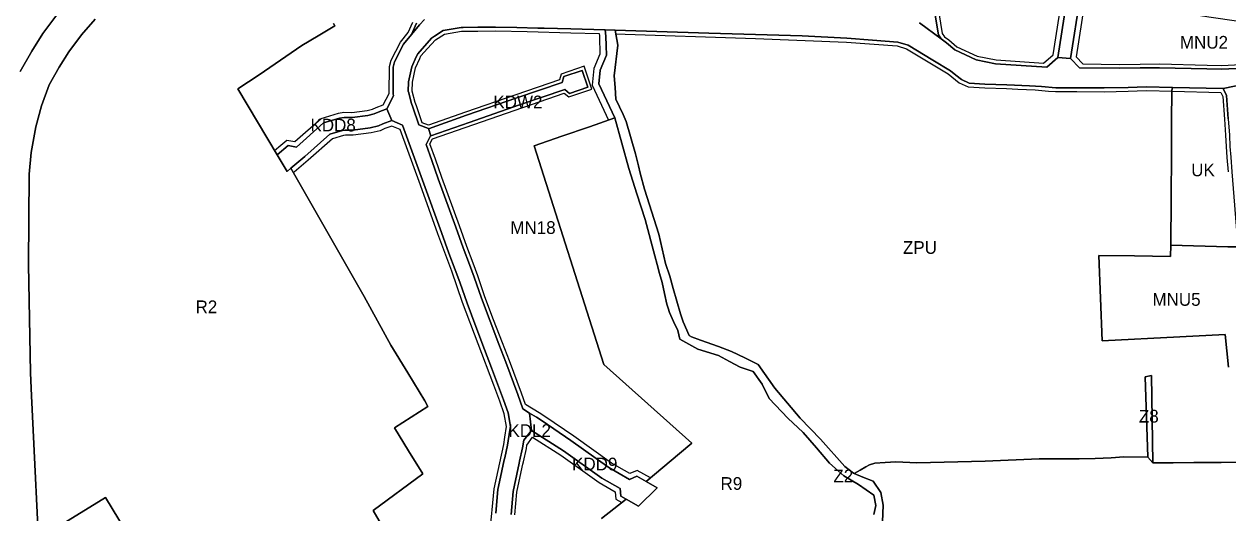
# Model space of a CAD drawing. Extents: x 7440055 to 7442242, y 5549003 to 5552256.
# Drawn here: x 7440555 to 7441503, y 5551138 to 5551522 of the extents above; entities that cross this region are included whole.
import ezdxf

# ---------------------------------------------------------------- set-up
doc = ezdxf.new("R2010")
doc.units = 0
for name, color, linetype in [('linie_rozgraniczajace', 7, 'Continuous'), ('linie_zabudowy_nieprzekraczalne', 7, 'Continuous'), ('oznaczenia_przeznaczen', 7, 'Continuous')]:
    doc.layers.add(name, color=color, linetype=linetype)

msp = doc.modelspace()

# ---------------------------------------------------------------- linework, layer by layer
at = {"layer": 'linie_rozgraniczajace'}
for points in [[(7441383.47, 5551585.26), (7441369.53, 5551496.02), (7441360.77, 5551488.28), (7441320.39, 5551491.07), (7441305.16, 5551494.15), (7441288.26, 5551501.88), (7441281.75, 5551507.55), (7441277.65, 5551510.58), (7441275.62, 5551513.88), (7441272.71, 5551530.74)], [(7441387.09, 5551543.58), (7441379.54, 5551495.17), (7441369.53, 5551496.02), (7441383.47, 5551585.26)], [(7440552.37, 5551484.85), (7440561.36, 5551501), (7440570.03, 5551514.74), (7440581.24, 5551529.61)], [(7440581.24, 5551529.61), (7440570.03, 5551514.74), (7440561.36, 5551501), (7440552.37, 5551484.85)], [(7440568.31, 5551084.03), (7440561.3, 5551229.74), (7440560.36, 5551247.97), (7440558.94, 5551333.21), (7440559.35, 5551404.19), (7440560.99, 5551421.23), (7440564.66, 5551441.32), (7440569.17, 5551457.85), (7440575.19, 5551474.44), (7440582.87, 5551488.25), (7440590.62, 5551500.52), (7440600.61, 5551513.79), (7440611.46, 5551526.06)], [(7440611.46, 5551526.06), (7440600.61, 5551513.79), (7440590.62, 5551500.52), (7440582.87, 5551488.25), (7440575.19, 5551474.44), (7440569.17, 5551457.85), (7440564.66, 5551441.32), (7440560.99, 5551421.23), (7440559.35, 5551404.19), (7440558.94, 5551333.21), (7440560.36, 5551247.97), (7440561.3, 5551229.74), (7440568.31, 5551084.03)], [(7440864.39, 5551522.89), (7440860.47, 5551514.03), (7440854.24, 5551506.48), (7440847.21, 5551492.58), (7440846.02, 5551488.33), (7440845.97, 5551467.36), (7440846.43, 5551465.88), (7440841.08, 5551455.6), (7440834.12, 5551453.05), (7440831.05, 5551451.58), (7440826.21, 5551450.42), (7440813.73, 5551448.76), (7440807.56, 5551448.87), (7440803.84, 5551448.27), (7440791.26, 5551444.5), (7440769.8, 5551425.47), (7440763.47, 5551426.67), (7440754.77, 5551419.34), (7440723.72, 5551471.36), (7440740.42, 5551482.41), (7440757.21, 5551493.91), (7440773.99, 5551505.41), (7440787, 5551513.13), (7440800.01, 5551520.84), (7440799.06, 5551522.6)], [(7440799.06, 5551522.6), (7440800.01, 5551520.84), (7440787, 5551513.13), (7440773.99, 5551505.41), (7440757.21, 5551493.91), (7440740.42, 5551482.41), (7440723.72, 5551471.36), (7440754.77, 5551419.34), (7440762.55, 5551406.31), (7440765.57, 5551408.85), (7440823.07, 5551307.95), (7440844.16, 5551269.66), (7440857.57, 5551247.82), (7440870.97, 5551225.98), (7440873.3, 5551221.47), (7440847.14, 5551204.57), (7440858.21, 5551186.49), (7440869.28, 5551168.42), (7440830.37, 5551139.67), (7440855.55, 5551096.35)], [(7440841.08, 5551455.6), (7440846.43, 5551465.88), (7440845.97, 5551467.36), (7440846.02, 5551488.33), (7440847.21, 5551492.58), (7440854.24, 5551506.48), (7440860.47, 5551514.03), (7440866.69, 5551521.58), (7440870.74, 5551525.79)], [(7440870.74, 5551525.79), (7440866.69, 5551521.58), (7440860.47, 5551514.03), (7440864.39, 5551522.89)], [(7441272.71, 5551530.74), (7441275.62, 5551513.88), (7441277.65, 5551510.58), (7441260.52, 5551523.24)], [(7441260.52, 5551523.24), (7441277.65, 5551510.58), (7441281.75, 5551507.55), (7441288.26, 5551501.88), (7441305.16, 5551494.15), (7441320.39, 5551491.07), (7441360.77, 5551488.28), (7441369.53, 5551496.02), (7441379.54, 5551495.17), (7441386.59, 5551487.9), (7441418.09, 5551487.55), (7441434.39, 5551487.74), (7441449.54, 5551487.92), (7441486.94, 5551487.06), (7441498.3, 5551486.67), (7441521.18, 5551487.82)], [(7441517.61, 5551475.36), (7441499.81, 5551471.5), (7441459.78, 5551472.46), (7441439.04, 5551472.95), (7441424.9, 5551472.43), (7441405.88, 5551471.99), (7441384.4, 5551472.11), (7441367.82, 5551472.16), (7441356.74, 5551473.02), (7441347.16, 5551473.76), (7441329.29, 5551474.56), (7441312.08, 5551475.02), (7441299.57, 5551475.72), (7441293.53, 5551478.67), (7441289.25, 5551482.12), (7441284.97, 5551485.58), (7441271.13, 5551493.91), (7441251.57, 5551505.53), (7441243.52, 5551508.12), (7441223.43, 5551509.64), (7441203.34, 5551511.15), (7441168.18, 5551512.88), (7441094.59, 5551515.18), (7441020.99, 5551517.47), (7441013.03, 5551517.77), (7440986.04, 5551518.48), (7440965.05, 5551518.98), (7440960.05, 5551519.09), (7440943.33, 5551519.46), (7440926.61, 5551519.83), (7440924.46, 5551519.89), (7440912.81, 5551519.77), (7440901.16, 5551519.65), (7440899.59, 5551519.64), (7440885.32, 5551517.28), (7440878.58, 5551512.84), (7440876.21, 5551511.27), (7440865.37, 5551498.82), (7440864.24, 5551496.37), (7440860.7, 5551488.71), (7440858.17, 5551476.9), (7440857.97, 5551469.18), (7440858.01, 5551469.07), (7440860.59, 5551459.78), (7440861.58, 5551457), (7440866.34, 5551443.07), (7440873.77, 5551440.02), (7440875.66, 5551434.26), (7440875.56, 5551434.23), (7440871.91, 5551427.55), (7440876.57, 5551414.95), (7440881.57, 5551400.63), (7440895.45, 5551362.45), (7440901.14, 5551346.29), (7440906.15, 5551333.12), (7440909.91, 5551323.26), (7440915.5, 5551306.79), (7440922.35, 5551288.57), (7440929.27, 5551270.45), (7440934.74, 5551256.2), (7440944.28, 5551230.79), (7440948.14, 5551219.49), (7440953.47, 5551216.3), (7440954.87, 5551202.51), (7440948.85, 5551195.01), (7440947.98, 5551188.98), (7440945.66, 5551178.47), (7440945.29, 5551176.84), (7440941.5, 5551159.61), (7440940.44, 5551154.55), (7440938.97, 5551136.46)], [(7441007.93, 5551475.12), (7441008.96, 5551486), (7441013.92, 5551497.72), (7441013.69, 5551505.16), (7441013.47, 5551512.61), (7441013.03, 5551517.77), (7441020.99, 5551517.47), (7441023.1, 5551505.78), (7441020.17, 5551481.56), (7441020.78, 5551472.39), (7441021.38, 5551463.21), (7441027.28, 5551451.22), (7441029.63, 5551445.5), (7441036.86, 5551420.19), (7441037.36, 5551418.15), (7441039.16, 5551410.84), (7441040.61, 5551404.89), (7441043.94, 5551392.31), (7441055.37, 5551357.09), (7441057.98, 5551345.56), (7441060.58, 5551334.02), (7441063.93, 5551324.03), (7441066.6, 5551314.17), (7441069.4, 5551304.23), (7441072.2, 5551294.3), (7441074.44, 5551288.02), (7441079.26, 5551277.23), (7441081.01, 5551276.13), (7441087.97, 5551273.64), (7441102.13, 5551268.56), (7441112.43, 5551264.68), (7441122.91, 5551259.64), (7441133.39, 5551254.59), (7441146.57, 5551235.75), (7441166.46, 5551212.18), (7441182.48, 5551195.8), (7441201.7, 5551174.39), (7441208.65, 5551169.02), (7441209.02, 5551168.74), (7441216.03, 5551165.84), (7441224.08, 5551162.79), (7441230.21, 5551153.9), (7441231.98, 5551143.95), (7441230.98, 5551117.63)], [(7441517.12, 5551177.56), (7441498.21, 5551177.47), (7441476.61, 5551177.35), (7441460.42, 5551177.25), (7441444.22, 5551177.16), (7441443.36, 5551245.71), (7441438.27, 5551244.8), (7441440.28, 5551181.48), (7441421.43, 5551181.89), (7441411.52, 5551181.14), (7441398.95, 5551180.66), (7441386.39, 5551180.17), (7441354.75, 5551180.31), (7441312.23, 5551178.44), (7441258.43, 5551177.15), (7441241.98, 5551178), (7441233.61, 5551177.4), (7441225.24, 5551176.81), (7441221.12, 5551175.51), (7441218.3, 5551173.93), (7441213.95, 5551171.5), (7441209.02, 5551168.74), (7441208.65, 5551169.02), (7441201.7, 5551174.39), (7441182.48, 5551195.8), (7441166.46, 5551212.18), (7441146.57, 5551235.75), (7441133.39, 5551254.59), (7441122.91, 5551259.64), (7441112.43, 5551264.68), (7441102.13, 5551268.56), (7441087.97, 5551273.64), (7441081.01, 5551276.13), (7441079.26, 5551277.23), (7441074.44, 5551288.02), (7441072.2, 5551294.3), (7441069.4, 5551304.23), (7441066.6, 5551314.17), (7441063.93, 5551324.03), (7441060.58, 5551334.02), (7441057.98, 5551345.56), (7441055.37, 5551357.09), (7441043.94, 5551392.31), (7441040.61, 5551404.89), (7441039.16, 5551410.84), (7441037.36, 5551418.15), (7441036.86, 5551420.19), (7441029.63, 5551445.5), (7441027.28, 5551451.22), (7441021.38, 5551463.21), (7441020.78, 5551472.39), (7441020.17, 5551481.56), (7441023.1, 5551505.78), (7441020.99, 5551517.47), (7441094.59, 5551515.18), (7441168.18, 5551512.88), (7441203.34, 5551511.15), (7441223.43, 5551509.64), (7441243.52, 5551508.12), (7441251.57, 5551505.53), (7441271.13, 5551493.91), (7441284.97, 5551485.58), (7441289.25, 5551482.12), (7441293.53, 5551478.67), (7441299.57, 5551475.72), (7441312.08, 5551475.02), (7441329.29, 5551474.56), (7441347.16, 5551473.76), (7441356.74, 5551473.02), (7441367.82, 5551472.16), (7441384.4, 5551472.11), (7441405.88, 5551471.99), (7441424.9, 5551472.43), (7441439.04, 5551472.95), (7441459.78, 5551472.46), (7441459.15, 5551470.04), (7441459.01, 5551445.55), (7441458.88, 5551421.05), (7441458.67, 5551384.69), (7441458.47, 5551348.32), (7441458.22, 5551339.48), (7441429.96, 5551339.88), (7441401.69, 5551340.27), (7441403.05, 5551306.63), (7441404.42, 5551272.98), (7441465.68, 5551276.14), (7441501.34, 5551277.98), (7441503.83, 5551252.33)], [(7441503.74, 5551447.63), (7441502.36, 5551466.11), (7441499.81, 5551471.5), (7441517.61, 5551475.36)], [(7441224.56, 5551136.62), (7441226.1, 5551143.57), (7441224.66, 5551151.71), (7441212.54, 5551160.19), (7441200.89, 5551166.81), (7441189.76, 5551176.86), (7441179.41, 5551188.94), (7441169.05, 5551201.03), (7441156.74, 5551212.26), (7441142.04, 5551227.85), (7441136.54, 5551238.91), (7441129.48, 5551249.06), (7441119.21, 5551252.35), (7441110.79, 5551256.96), (7441102.37, 5551261.58), (7441085.93, 5551266.65), (7441078.92, 5551270.57), (7441071.91, 5551274.48), (7441070.14, 5551281.3), (7441066.92, 5551288.37), (7441063.71, 5551295.45), (7441062.67, 5551298.73), (7441061.63, 5551302.02), (7441059.71, 5551310.46), (7441057.78, 5551318.9), (7441055.89, 5551326.18), (7441054.02, 5551333.12), (7441052.16, 5551340.05), (7441044.51, 5551368.57), (7441038.05, 5551388.68), (7441031.59, 5551408.78), (7441026.03, 5551428.58), (7441020.48, 5551448.38), (7441007.93, 5551475.12)], [(7440870.3, 5551396.52), (7440853.38, 5551442.77), (7440845, 5551446.38), (7440841.08, 5551455.6)], [(7440957.02, 5551426.53), (7440978.88, 5551434.05), (7441000.62, 5551441.54), (7441020.48, 5551448.38), (7441026.03, 5551428.58), (7441031.59, 5551408.78), (7441038.05, 5551388.68), (7441044.51, 5551368.57), (7441052.16, 5551340.05), (7441054.02, 5551333.12), (7441055.89, 5551326.18), (7441057.78, 5551318.9), (7441059.71, 5551310.46), (7441061.63, 5551302.02), (7441062.67, 5551298.73), (7441063.71, 5551295.45), (7441066.92, 5551288.37), (7441070.14, 5551281.3), (7441071.91, 5551274.48), (7441078.92, 5551270.57), (7441085.93, 5551266.65), (7441102.37, 5551261.58), (7441110.79, 5551256.96), (7441119.21, 5551252.35), (7441129.48, 5551249.06), (7441136.54, 5551238.91), (7441142.04, 5551227.85), (7441156.74, 5551212.26), (7441169.05, 5551201.03), (7441179.41, 5551188.94), (7441189.76, 5551176.86), (7441200.89, 5551166.81), (7441212.54, 5551160.19), (7441224.66, 5551151.71), (7441226.1, 5551143.57), (7441224.56, 5551136.62)], [(7440855.55, 5551096.35), (7440830.37, 5551139.67), (7440869.28, 5551168.42), (7440858.21, 5551186.49), (7440847.14, 5551204.57), (7440873.3, 5551221.47), (7440870.97, 5551225.98), (7440857.57, 5551247.82), (7440844.16, 5551269.66), (7440823.07, 5551307.95), (7440765.57, 5551408.85), (7440776.57, 5551418.11), (7440796.24, 5551435.55), (7440806.09, 5551438.5), (7440808.27, 5551438.86), (7440814.3, 5551438.75), (7440828.04, 5551440.58), (7440834.41, 5551442.1), (7440838.01, 5551443.83), (7440845, 5551446.38), (7440853.38, 5551442.77), (7440870.3, 5551396.52), (7440884.15, 5551358.41), (7440889.87, 5551342.16), (7440894.94, 5551328.85), (7440898.62, 5551319.19), (7440904.2, 5551302.74), (7440911.13, 5551284.32), (7440918.06, 5551266.16), (7440923.52, 5551251.94), (7440932.98, 5551226.74), (7440936.48, 5551216.5), (7440938.34, 5551205.77), (7440937.85, 5551202.89), (7440936.17, 5551191.13), (7440933.95, 5551181.1), (7440933.58, 5551179.46), (7440929.76, 5551162.12), (7440928.54, 5551156.26), (7440927.02, 5551137.61)], [(7441081.3, 5551192.61), (7441012.02, 5551254.53), (7440957.02, 5551426.53)], [(7440927.02, 5551137.61), (7440928.54, 5551156.26), (7440929.76, 5551162.12), (7440933.58, 5551179.46), (7440933.95, 5551181.1), (7440936.17, 5551191.13), (7440937.85, 5551202.89), (7440938.34, 5551205.77), (7440936.48, 5551216.5), (7440932.98, 5551226.74), (7440923.52, 5551251.94), (7440918.06, 5551266.16), (7440911.13, 5551284.32), (7440904.2, 5551302.74), (7440898.62, 5551319.19), (7440894.94, 5551328.85), (7440889.87, 5551342.16), (7440884.15, 5551358.41), (7440870.3, 5551396.52)], [(7441503.83, 5551252.33), (7441501.34, 5551277.98), (7441465.68, 5551276.14), (7441404.42, 5551272.98), (7441403.05, 5551306.63), (7441401.69, 5551340.27), (7441429.96, 5551339.88), (7441458.22, 5551339.48), (7441458.47, 5551348.32), (7441503.41, 5551347.09), (7441511.48, 5551346.99)], [(7440938.97, 5551136.46), (7440940.44, 5551154.55), (7440941.5, 5551159.61), (7440945.29, 5551176.84), (7440945.66, 5551178.47), (7440947.98, 5551188.98), (7440948.85, 5551195.01), (7440954.87, 5551202.51), (7440980.3, 5551186.52), (7441010.46, 5551164.98), (7441024.78, 5551156.88), (7441025.24, 5551150.89), (7441029.47, 5551148.49), (7441010.11, 5551133.47)], [(7441010.11, 5551133.47), (7441029.47, 5551148.49), (7441039.18, 5551142.99), (7441054.04, 5551157.56), (7441045.34, 5551162.48), (7441071.61, 5551184.49), (7441081.3, 5551192.61)], [(7441209.02, 5551168.74), (7441213.95, 5551171.5), (7441218.3, 5551173.93), (7441221.12, 5551175.51), (7441225.24, 5551176.81), (7441233.61, 5551177.4), (7441241.98, 5551178), (7441258.43, 5551177.15), (7441312.23, 5551178.44), (7441354.75, 5551180.31), (7441386.39, 5551180.17), (7441398.95, 5551180.66), (7441411.52, 5551181.14), (7441421.43, 5551181.89), (7441440.28, 5551181.48), (7441444.22, 5551177.16), (7441460.42, 5551177.25), (7441476.61, 5551177.35), (7441498.21, 5551177.47), (7441517.12, 5551177.56)], [(7441244.59, 5551051.25), (7441242.8, 5551055.32), (7441237.46, 5551070.83), (7441234.84, 5551079.14), (7441233.01, 5551093.6), (7441230.98, 5551117.63), (7441231.98, 5551143.95), (7441230.21, 5551153.9), (7441224.08, 5551162.79), (7441216.03, 5551165.84), (7441209.02, 5551168.74)], [(7440639.69, 5551116.53), (7440619.62, 5551149.85), (7440579.81, 5551125.56)], [(7440579.81, 5551125.56), (7440619.62, 5551149.85), (7440639.69, 5551116.53)]]:
    msp.add_lwpolyline(points, dxfattribs=at)
for points in [[(7441379.54, 5551495.17), (7441387.09, 5551543.58), (7441401.52, 5551541.5), (7441419.5, 5551538.9), (7441488.41, 5551528.05), (7441511.96, 5551524.56), (7441531.09, 5551521.72), (7441580.62, 5551513.17), (7441627.66, 5551505.05), (7441626.12, 5551492.12), (7441619.41, 5551486.36), (7441604.8, 5551486.85), (7441588.52, 5551487.45), (7441538.54, 5551488.01), (7441529, 5551488.21), (7441521.18, 5551487.82), (7441498.3, 5551486.67), (7441486.94, 5551487.06), (7441449.54, 5551487.92), (7441434.39, 5551487.74), (7441418.09, 5551487.55), (7441386.59, 5551487.9)], [(7440857.97, 5551469.18), (7440858.17, 5551476.9), (7440860.7, 5551488.71), (7440864.24, 5551496.37), (7440865.37, 5551498.82), (7440876.21, 5551511.27), (7440878.58, 5551512.84), (7440885.32, 5551517.28), (7440899.59, 5551519.64), (7440901.16, 5551519.65), (7440912.81, 5551519.77), (7440924.46, 5551519.89), (7440926.61, 5551519.83), (7440943.33, 5551519.46), (7440960.05, 5551519.09), (7440965.05, 5551518.98), (7440986.04, 5551518.48), (7441013.03, 5551517.77), (7441013.47, 5551512.61), (7441013.69, 5551505.16), (7441013.92, 5551497.72), (7441008.96, 5551486), (7441007.93, 5551475.12), (7441020.48, 5551448.38), (7441000.62, 5551441.54), (7440978.88, 5551434.05), (7440957.02, 5551426.53), (7441012.02, 5551254.53), (7441081.3, 5551192.61), (7441071.61, 5551184.49), (7441045.34, 5551162.48), (7441037.89, 5551166.69), (7441032.21, 5551164.16), (7441015.85, 5551173.42), (7440986.03, 5551194.72), (7440963.32, 5551210.27), (7440958.8, 5551213.12), (7440953.47, 5551216.3), (7440948.14, 5551219.49), (7440944.28, 5551230.79), (7440934.74, 5551256.2), (7440929.27, 5551270.45), (7440922.35, 5551288.57), (7440915.5, 5551306.79), (7440909.91, 5551323.26), (7440906.15, 5551333.12), (7440901.14, 5551346.29), (7440895.45, 5551362.45), (7440881.57, 5551400.63), (7440876.57, 5551414.95), (7440871.91, 5551427.55), (7440875.56, 5551434.23), (7440875.66, 5551434.26), (7440905.85, 5551444.85), (7440945.46, 5551458.6), (7440981.16, 5551470.68), (7440984.95, 5551467.74), (7440999.27, 5551472.59), (7440994.78, 5551485.85), (7440980.43, 5551480.99), (7440979.2, 5551476.35), (7440943.51, 5551464.27), (7440903.87, 5551450.52), (7440873.91, 5551439.97), (7440873.77, 5551440.02), (7440866.34, 5551443.07), (7440861.58, 5551457), (7440860.59, 5551459.78), (7440858.01, 5551469.07)], [(7440873.77, 5551440.02), (7440873.91, 5551439.97), (7440903.87, 5551450.52), (7440943.51, 5551464.27), (7440979.2, 5551476.35), (7440980.43, 5551480.99), (7440994.78, 5551485.85), (7440999.27, 5551472.59), (7440984.95, 5551467.74), (7440981.16, 5551470.68), (7440945.46, 5551458.6), (7440905.85, 5551444.85), (7440875.66, 5551434.26)], [(7441458.47, 5551348.32), (7441458.67, 5551384.69), (7441458.88, 5551421.05), (7441459.01, 5551445.55), (7441459.15, 5551470.04), (7441459.78, 5551472.46), (7441499.81, 5551471.5), (7441502.36, 5551466.11), (7441503.74, 5551447.63), (7441504.59, 5551434.9), (7441504.95, 5551426.05), (7441505.67, 5551417.51), (7441506.57, 5551406.14), (7441511.08, 5551350.28), (7441511.48, 5551346.99), (7441503.41, 5551347.09)], [(7440754.77, 5551419.34), (7440763.47, 5551426.67), (7440769.8, 5551425.47), (7440791.26, 5551444.5), (7440803.84, 5551448.27), (7440807.56, 5551448.87), (7440813.73, 5551448.76), (7440826.21, 5551450.42), (7440831.05, 5551451.58), (7440834.12, 5551453.05), (7440841.08, 5551455.6), (7440845, 5551446.38), (7440838.01, 5551443.83), (7440834.41, 5551442.1), (7440828.04, 5551440.58), (7440814.3, 5551438.75), (7440808.27, 5551438.86), (7440806.09, 5551438.5), (7440796.24, 5551435.55), (7440776.57, 5551418.11), (7440765.57, 5551408.85), (7440762.55, 5551406.31)], [(7441440.28, 5551181.48), (7441438.27, 5551244.8), (7441443.36, 5551245.71), (7441444.22, 5551177.16)], [(7440953.47, 5551216.3), (7440958.8, 5551213.12), (7440963.32, 5551210.27), (7440986.03, 5551194.72), (7441015.85, 5551173.42), (7441032.21, 5551164.16), (7441037.89, 5551166.69), (7441045.34, 5551162.48), (7441054.04, 5551157.56), (7441039.18, 5551142.99), (7441029.47, 5551148.49), (7441025.24, 5551150.89), (7441024.78, 5551156.88), (7441010.46, 5551164.98), (7440980.3, 5551186.52), (7440954.87, 5551202.51)]]:
    msp.add_lwpolyline(points, close=True, dxfattribs=at)
at = {"layer": 'linie_zabudowy_nieprzekraczalne'}
for points in [[(7441463.8, 5552039.31), (7441463.8, 5552039.3), (7441453.93, 5551976.28), (7441444.62, 5551905.81), (7441430.25, 5551808.87), (7441427.35, 5551791.63), (7441425.39, 5551774.19), (7441420.05, 5551732.63), (7441419.07, 5551719.65), (7441412, 5551677.19), (7441397.51, 5551584.45), (7441383.8, 5551496.52), (7441389.28, 5551490.87), (7441418.09, 5551490.55), (7441434.35, 5551490.74), (7441449.56, 5551490.92), (7441487.03, 5551490.06), (7441498.28, 5551489.67), (7441524.19, 5551490.97)], [(7441358.32, 5551491.46), (7441365.8, 5551498.06), (7441394.14, 5551679.5)], [(7440752.69, 5551422.82), (7440757.52, 5551426.88), (7440762.35, 5551430.95), (7440765.48, 5551430.36), (7440768.61, 5551429.76), (7440789.27, 5551448.08), (7440802.95, 5551452.17), (7440807.28, 5551452.87), (7440813.5, 5551452.76), (7440825.48, 5551454.36), (7440829.7, 5551455.37), (7440832.57, 5551456.74), (7440838.28, 5551458.83), (7440842.97, 5551467.54), (7440843.02, 5551488.75), (7440844.53, 5551493.94), (7440851.71, 5551508.13), (7440857.89, 5551515.62), (7440861.47, 5551523.7)], [(7441275.69, 5551531.12), (7441278.48, 5551514.96), (7441280.2, 5551512.16), (7441283.63, 5551509.89), (7441289.9, 5551504.42), (7441306.09, 5551497.02), (7441320.8, 5551494.05), (7441358.32, 5551491.46)], [(7441048.62, 5551165.22), (7441038.1, 5551171.17), (7441032.42, 5551168.64), (7441018, 5551176.8), (7440988.32, 5551197.99), (7440965.52, 5551213.61), (7440960.89, 5551216.53), (7440950.19, 5551222.92), (7440947.1, 5551231.81), (7440937.54, 5551257.26), (7440932.07, 5551271.53), (7440925.15, 5551289.64), (7440918.33, 5551307.79), (7440912.73, 5551324.27), (7440908.96, 5551334.19), (7440903.95, 5551347.32), (7440898.27, 5551363.46), (7440884.4, 5551401.63), (7440879.4, 5551415.96), (7440874.94, 5551428.01), (7440876.92, 5551432.05), (7440980.7, 5551467.88), (7440984.48, 5551464.94), (7441002.44, 5551471.02), (7440996.34, 5551489.02), (7440978.36, 5551482.93), (7440977.13, 5551478.29), (7440942.7, 5551466.64), (7440903.05, 5551452.88), (7440873.98, 5551442.64), (7440868.95, 5551444.7), (7440864.41, 5551457.99), (7440863.45, 5551460.69), (7440860.98, 5551469.56), (7440861.17, 5551476.55), (7440863.57, 5551487.75), (7440866.96, 5551495.11), (7440867.91, 5551497.17), (7440873.01, 5551503.03), (7440879.34, 5551509.75), (7440886.44, 5551514.42), (7440899.85, 5551516.64), (7440901.19, 5551516.65), (7440912.83, 5551516.77), (7440926.58, 5551516.83), (7440951.62, 5551516.28), (7440985.96, 5551515.48), (7441008.25, 5551514.89), (7441008.43, 5551512.89), (7441008.47, 5551512.32), (7441008.89, 5551498.66), (7441004.06, 5551487.24), (7441002.83, 5551474.23), (7441015.72, 5551446.74)], [(7441020.9, 5551514.47), (7441131.28, 5551511.03), (7441203.16, 5551508.15), (7441242.94, 5551505.16), (7441250.32, 5551502.78), (7441283.25, 5551483.11), (7441291.91, 5551476.12), (7441298.8, 5551472.76), (7441311.96, 5551472.02), (7441329.18, 5551471.56), (7441338.07, 5551471.16), (7441351.75, 5551470.4), (7441362.05, 5551469.6), (7441367.7, 5551469.16), (7441384.39, 5551469.11), (7441405.9, 5551468.99), (7441424.99, 5551469.43), (7441439.06, 5551469.94), (7441459.71, 5551469.46), (7441497.89, 5551468.54), (7441499.41, 5551465.33), (7441500.75, 5551447.42), (7441501.59, 5551434.74), (7441501.95, 5551425.87), (7441502.68, 5551417.27), (7441503.58, 5551405.9)], [(7440922.16, 5551121.03), (7440925.57, 5551156.73), (7440933.21, 5551191.66), (7440934.04, 5551197.45), (7440935.3, 5551205.74), (7440933.57, 5551215.76), (7440930.16, 5551225.73), (7440925.44, 5551238.28), (7440900.74, 5551303.32), (7440892.12, 5551327.84), (7440881.33, 5551357.38), (7440867.48, 5551395.49), (7440851.53, 5551439.22), (7440844.88, 5551442.08), (7440839.57, 5551440.14), (7440835.76, 5551438.31), (7440828.77, 5551436.64), (7440814.53, 5551434.74), (7440808.56, 5551434.85), (7440806.98, 5551434.59), (7440798.24, 5551431.98), (7440779.19, 5551415.09), (7440768.14, 5551405.79)], [(7440941.95, 5551136.17), (7440943.41, 5551154.12), (7440944.43, 5551158.98), (7440948.22, 5551176.19), (7440948.59, 5551177.82), (7440950.93, 5551188.44), (7440951.32, 5551191.14), (7440955.75, 5551197.22), (7440978.07, 5551183.2), (7441008.31, 5551161.6), (7441020.95, 5551154.45), (7441021.41, 5551148.45), (7441026.04, 5551145.83)]]:
    msp.add_lwpolyline(points, dxfattribs=at)

# ---------------------------------------------------------------- texts
at = {"layer": 'oznaczenia_przeznaczen'}
for s, p in [('MNU2', (7441465.62, 5551502.94)), ('KDW2', (7440924.98, 5551455.98)), ('KDD8', (7440780.93, 5551437.79)), ('UK', (7441474.53, 5551402.54)), ('MN18', (7440938.3, 5551357.2)), ('ZPU', (7441247.54, 5551341.52)), ('R2', (7440690.4, 5551294.86)), ('MNU5', (7441444.02, 5551300.65)), ('Z8', (7441433.34, 5551208.82)), ('KDL2', (7440936.84, 5551197.51)), ('KDD9', (7440986.96, 5551171.2)), ('Z2', (7441192.7, 5551161.81)), ('R9', (7441103.84, 5551155.89))]:
    msp.add_text(s, height=10, dxfattribs=at).set_placement(p)

doc.saveas('drawing.dxf')
